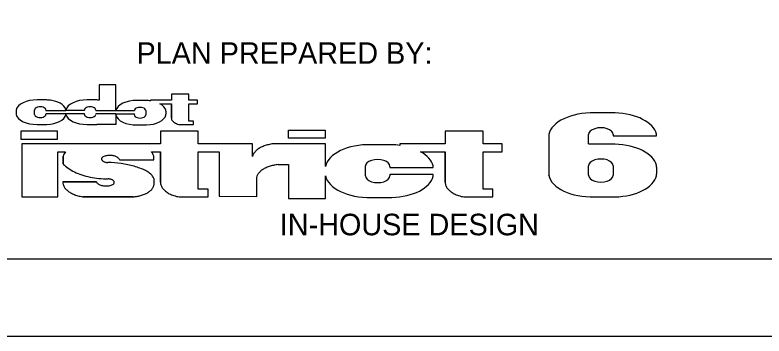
# Model space of a CAD drawing. Extents: x 0 to 34, y 0 to 22.
# Drawn here: x 2.822 to 7.693, y 0 to 2.086 of the extents above; entities that cross this region are included whole.
import ezdxf

# ---------------------------------------------------------------- set-up
doc = ezdxf.new("R2010")
doc.units = 0
for name, color, linetype in [('SC_Scratch9', 7, 'Continuous'), ('SH_Border', 7, 'Continuous'), ('SH_Cut_Line', 7, 'Continuous'), ('SH_Data', 7, 'Continuous')]:
    doc.layers.add(name, color=color, linetype=linetype)

msp = doc.modelspace()

# ---------------------------------------------------------------- linework, layer by layer
at = {"layer": 'SH_Border'}
msp.add_lwpolyline([(0, 0), (34, 0), (34, 22), (0, 22)], close=True, dxfattribs=at)
at = {"layer": 'SH_Cut_Line'}
for p, q in [((3.3699, 1.632), (3.3699, 1.5331)), ((3.4787, 1.632), (3.3699, 1.632)), ((3.4787, 1.4652), (3.4787, 1.632)), ((3.8392, 1.5717), (3.8392, 1.5336)), ((3.9533, 1.5717), (3.8392, 1.5717)), ((3.9533, 1.5336), (3.9533, 1.5717)), ((2.9918, 1.534), (2.9668, 1.534)), ((3.029, 1.534), (2.9918, 1.534)), ((3.3164, 1.534), (3.2914, 1.534)), ((3.3537, 1.534), (3.3164, 1.534)), ((3.6411, 1.5305), (3.616, 1.5305)), ((3.6783, 1.5305), (3.6411, 1.5305)), ((3.8392, 1.5336), (3.703, 1.5336)), ((3.703, 1.5336), (3.703, 1.5286)), ((4.0103, 1.5336), (3.9533, 1.5336)), ((4.0103, 1.5094), (4.0103, 1.5336)), ((2.8294, 1.4686), (2.8294, 1.4407)), ((2.9496, 1.4406), (2.9494, 1.4686)), ((3.0235, 1.4686), (3.0235, 1.4652)), ((3.0235, 1.4652), (3.1541, 1.4652)), ((3.1541, 1.4652), (3.1538, 1.4702)), ((3.1541, 1.4686), (3.1541, 1.4652)), ((3.2741, 1.4652), (3.1541, 1.4652)), ((3.2741, 1.4652), (3.2741, 1.4686)), ((3.3483, 1.4686), (3.3483, 1.4652)), ((3.3483, 1.4652), (3.4787, 1.4652)), ((3.4787, 1.4652), (3.4786, 1.4702)), ((3.4787, 1.4652), (3.4786, 1.4702)), ((3.4787, 1.4652), (3.5987, 1.4652)), ((3.6728, 1.4652), (3.6728, 1.4617)), ((3.6728, 1.4617), (3.6728, 1.4408)), ((3.7648, 1.5094), (3.8392, 1.5094)), ((3.8033, 1.4617), (3.8032, 1.4668)), ((3.8033, 1.4617), (3.8033, 1.4408)), ((3.8392, 1.4174), (3.8392, 1.5094)), ((3.8392, 1.5094), (3.8392, 1.4174)), ((3.9533, 1.397), (3.9533, 1.5094)), ((3.9533, 1.5094), (4.0103, 1.5094)), ((3.0235, 1.4442), (3.0235, 1.4408)), ((3.1541, 1.4442), (3.0235, 1.4442)), ((3.1538, 1.4391), (3.1541, 1.4442)), ((3.2742, 1.4442), (3.1541, 1.4442)), ((3.1541, 1.4442), (3.1541, 1.4407)), ((3.2743, 1.4407), (3.2742, 1.4442)), ((3.3483, 1.4442), (3.3483, 1.4408)), ((3.4787, 1.4442), (3.3483, 1.4442)), ((3.4786, 1.4392), (3.4787, 1.4442)), ((3.4786, 1.4392), (3.4787, 1.4442)), ((3.4787, 1.4442), (3.4957, 1.4442)), ((3.4787, 1.4442), (3.4787, 1.3754)), ((3.4957, 1.4442), (3.5988, 1.4442)), ((3.5988, 1.4372), (3.5988, 1.4442)), ((3.6728, 1.4408), (3.6728, 1.4373)), ((3.8032, 1.4357), (3.8033, 1.4408)), ((6.6439, 1.4497), (6.5898, 1.4497)), ((6.7243, 1.4497), (6.6439, 1.4497)), ((2.9668, 1.3754), (2.9918, 1.3754)), ((2.9918, 1.3754), (3.029, 1.3754)), ((3.2914, 1.3754), (3.3164, 1.3754)), ((3.3164, 1.3754), (3.3537, 1.3754)), ((3.4787, 1.3754), (3.3537, 1.3754)), ((3.4787, 1.3908), (3.4787, 1.3898)), ((3.616, 1.3719), (3.6411, 1.3719)), ((3.6411, 1.3719), (3.6783, 1.3719)), ((3.8951, 1.3736), (3.9828, 1.3736)), ((3.9828, 1.397), (3.9533, 1.397)), ((3.9828, 1.3736), (3.9828, 1.397)), ((2.8606, 1.3321), (2.8606, 1.2797)), ((3.0982, 1.3321), (2.8606, 1.3321)), ((3.0982, 1.2797), (3.0982, 1.3321)), ((3.7683, 1.3321), (3.7683, 1.2499)), ((4.0146, 1.3321), (3.7683, 1.3321)), ((4.0146, 1.2499), (4.0146, 1.3321)), ((4.6014, 1.3371), (4.8386, 1.3371)), ((4.6014, 1.2848), (4.6014, 1.3371)), ((4.8386, 1.3371), (4.8386, 1.2848)), ((5.6201, 1.3321), (5.6201, 1.2499)), ((5.8664, 1.3321), (5.6201, 1.3321)), ((5.8664, 1.2499), (5.8664, 1.3321)), ((2.8606, 1.2797), (3.0982, 1.2797)), ((4.8386, 1.2848), (4.6014, 1.2848)), ((6.2935, 1.3087), (6.2932, 1.0451)), ((6.2935, 1.3087), (6.2935, 1.3103)), ((6.5528, 1.2481), (6.5523, 1.3087)), ((6.7123, 1.3087), (6.7123, 1.3013)), ((6.7123, 1.3013), (6.9943, 1.3013)), ((6.9943, 1.3013), (6.9939, 1.3121)), ((2.866, 1.2499), (2.866, 0.9041)), ((3.5751, 1.2499), (2.866, 1.2499)), ((3.7683, 1.2499), (3.4431, 1.2499)), ((4.3671, 1.2499), (4.0146, 1.2499)), ((4.3671, 1.1659), (4.3671, 1.2499)), ((4.8418, 1.2499), (4.5098, 1.2499)), ((4.8418, 1.1021), (4.8418, 1.2499)), ((5.1923, 1.2431), (5.1382, 1.2431)), ((5.2727, 1.2431), (5.1923, 1.2431)), ((5.6201, 1.2499), (5.3259, 1.2499)), ((5.3259, 1.2499), (5.3259, 1.2389)), ((5.9897, 1.2499), (5.8664, 1.2499)), ((5.9897, 1.1976), (5.9897, 1.2499)), ((6.6439, 1.2465), (6.5898, 1.2465)), ((6.7243, 1.2465), (6.6439, 1.2465)), ((3.101, 0.9041), (3.101, 1.1976)), ((3.101, 1.1976), (3.1514, 1.1973)), ((3.1363, 1.1181), (3.1363, 1.1695)), ((3.1363, 1.1695), (3.1363, 1.1181)), ((3.7091, 1.1976), (3.7683, 1.1976)), ((3.7254, 1.1458), (3.7254, 1.1693)), ((3.7683, 0.9989), (3.7683, 1.1976)), ((3.7683, 1.1976), (3.7683, 0.9989)), ((4.0146, 1.1976), (4.1507, 1.1976)), ((4.0146, 0.9547), (4.0146, 1.1976)), ((4.1507, 1.1976), (4.1507, 0.9091)), ((5.4593, 1.1976), (5.6201, 1.1976)), ((5.6201, 0.9989), (5.6201, 1.1976)), ((5.6201, 1.1976), (5.6201, 0.9989)), ((5.8664, 0.9547), (5.8664, 1.1976)), ((5.8664, 1.1976), (5.9897, 1.1976)), ((3.503, 1.1458), (3.7254, 1.1458)), ((4.5337, 1.1139), (4.6014, 1.1139)), ((4.6014, 1.1139), (4.6014, 0.8939)), ((5.1011, 1.0416), (5.1007, 1.1021)), ((5.2607, 1.1021), (5.2607, 1.0946)), ((5.2607, 1.0946), (5.5427, 1.0946)), ((5.5427, 1.0946), (5.5423, 1.1055)), ((6.5528, 1.0451), (6.5523, 1.1055)), ((6.7123, 1.1055), (6.7123, 1.098)), ((6.7123, 1.098), (6.7123, 1.0527)), ((6.9943, 1.098), (6.9939, 1.1089)), ((6.9943, 1.098), (6.9943, 1.0527)), ((3.7258, 1.0237), (3.7258, 0.9799)), ((4.3942, 0.9074), (4.3942, 1.0299)), ((4.8418, 0.8939), (4.8418, 1.0416)), ((5.2607, 1.0493), (5.2607, 1.0418)), ((5.5427, 1.0493), (5.2607, 1.0493)), ((5.5423, 1.0383), (5.5427, 1.0493)), ((6.2935, 1.0436), (6.2935, 1.0451)), ((6.7123, 1.0527), (6.7123, 1.0452)), ((6.9939, 1.0418), (6.9943, 1.0527)), ((3.1335, 1.0031), (3.3519, 1.0031)), ((3.3519, 1.0031), (3.1335, 1.0031)), ((4.0783, 0.9547), (4.0146, 0.9547)), ((4.0783, 0.9041), (4.0783, 0.9547)), ((5.9301, 0.9547), (5.8664, 0.9547)), ((5.9301, 0.9041), (5.9301, 0.9547)), ((2.866, 0.9041), (3.101, 0.9041)), ((3.5902, 0.9048), (3.2625, 0.9048)), ((3.2625, 0.9048), (3.5902, 0.9048)), ((3.8891, 0.9041), (4.0783, 0.9041)), ((4.1507, 0.9091), (4.3942, 0.9074)), ((4.6014, 0.8939), (4.8418, 0.8939)), ((5.1382, 0.9006), (5.1923, 0.9006)), ((5.1923, 0.9006), (5.2727, 0.9006)), ((5.7409, 0.9041), (5.9301, 0.9041)), ((6.5898, 0.9041), (6.6439, 0.9041)), ((6.6439, 0.9041), (6.7243, 0.9041))]:
    msp.add_line(p, q, dxfattribs=at)
for centre, major_axis, start_param, end_param in [((2.9607, 1.4602), (0.1322, 0), 1.524851, 3.026464), ((3.0229, 1.4602), (0.1321, 0), 1.335517, 1.524729), ((3.0228, 1.4602), (0.1322, 0), 0.793644, 1.335258), ((3.0229, 1.4602), (0.1321, 0), 0.136005, 0.793914), ((3.2854, 1.4602), (0.1322, 0), 1.524851, 3.026464), ((3.3476, 1.4602), (0.1321, 0), 1.401291, 1.524729), ((3.61, 1.4567), (0.1322, 0), 1.524851, 3.026464), ((3.6722, 1.4568), (0.1321, 0), 1.335517, 1.524729), ((2.9864, 1.4687), (0.037, 0), 6.283105, 9.424778), ((3.3111, 1.4687), (0.037, 0), 6.283105, 9.424778), ((3.6357, 1.4652), (0.037, 0), 6.283105, 9.424778), ((3.6722, 1.4568), (0.1321, 0), 0.136005, 0.793914), ((2.9606, 1.4492), (0.1321, 0), 3.256471, 4.758084), ((2.9864, 1.4407), (0.037, 0), 3.141637, 6.283987), ((3.0229, 1.4492), (0.1322, 0), 4.758334, 6.147057), ((3.2853, 1.4492), (0.1321, 0), 3.256471, 4.758084), ((3.3111, 1.4407), (0.037, 0), 3.141637, 6.283987), ((3.6099, 1.4457), (0.1321, 0), 3.256471, 4.758084), ((3.6357, 1.4372), (0.037, 0), 3.141637, 6.283987), ((3.6722, 1.4457), (0.1322, 0), 4.758334, 6.147057), ((3.9234, 1.4174), (0.0842, 0), 3.141424, 3.346546), ((6.5767, 1.2905), (0.2854, 0), 1.524851, 3.026464), ((6.7111, 1.2905), (0.2854, 0), 0.136005, 1.524729), ((3.9226, 1.4173), (0.0834, 0), 3.346554, 3.553012), ((3.922, 1.4172), (0.0827, 0), 3.553048, 3.760669), ((3.9216, 1.417), (0.0822, 0), 3.760726, 3.969135), ((3.9215, 1.417), (0.0821, 0), 3.969205, 4.177885), ((3.9215, 1.417), (0.0822, 0), 4.177955, 4.386342), ((6.6323, 1.3088), (0.08, 0), 6.283105, 9.424778), ((4.5369, 1.1553), (0.171, 0), 2.291032, 2.475806), ((4.5382, 1.1545), (0.1729, 0), 2.107607, 2.291041), ((4.5391, 1.1537), (0.1746, 0), 1.925382, 2.107637), ((4.5395, 1.1531), (0.1758, 0), 1.744044, 1.925429), ((5.125, 1.0838), (0.2854, 0), 1.524851, 3.026464), ((5.2594, 1.0838), (0.2854, 0), 1.335517, 1.524729), ((6.5767, 1.0872), (0.2854, 0), 1.524851, 1.654748), ((6.7111, 1.0872), (0.2854, 0), 0.136005, 1.524729), ((3.2846, 1.1593), (0.1495, 0), 2.843627, 3.018215), ((3.2854, 1.1592), (0.1504, 0), 2.669663, 2.843584), ((3.4381, 1.1371), (0.0656, 0), 1.981803, 2.175423), ((3.4383, 1.1368), (0.0662, 0), 1.789333, 1.981853), ((3.4384, 1.1367), (0.0665, 0), 1.597511, 1.789398), ((3.4384, 1.1366), (0.0665, 0), 1.405775, 1.597582), ((3.4384, 1.1368), (0.0663, 0), 1.213551, 1.405843), ((3.4386, 1.137), (0.0658, 0), 1.020333, 1.213606), ((3.5469, 1.1548), (0.1795, 0), 0.331392, 0.440283), ((3.5408, 1.1536), (0.186, 0), 0.151141, 0.33161), ((4.5332, 1.1565), (0.1666, 0), 2.849219, 3.037192), ((4.5342, 1.1563), (0.1677, 0), 2.66195, 2.849165), ((4.5355, 1.1559), (0.1692, 0), 2.47582, 2.661914), ((5.2594, 1.0838), (0.2854, 0), 0.136005, 0.793914), ((3.4257, 1.151), (0.0404, 0), 3.014859, 3.224424), ((3.4258, 1.151), (0.0405, 0), 3.224512, 3.433796), ((3.4258, 1.151), (0.0405, 0), 2.805634, 3.014772), ((3.426, 1.151), (0.0408, 0), 3.43387, 3.642217), ((3.4261, 1.1509), (0.0409, 0), 2.597484, 2.805565), ((3.4264, 1.1511), (0.0412, 0), 3.642263, 3.849188), ((3.4377, 1.1375), (0.0649, 0), 2.175395, 2.370427), ((3.4268, 1.1513), (0.0417, 0), 3.8492, 4.054466), ((3.4271, 1.1515), (0.0422, 0), 4.054443, 4.258098), ((3.4273, 1.1517), (0.0426, 0), 4.258045, 4.460395), ((3.4273, 1.1519), (0.0429, 0), 4.460322, 4.661876), ((3.4097, 0.8981), (0.4116, 0), 1.316143, 1.533129), ((3.439, 1.1374), (0.0651, 0), 0.82575, 1.020367), ((3.4395, 1.1377), (0.0643, 0), 0.629627, 0.825757), ((3.44, 1.1379), (0.0636, 0), 0.432021, 0.629605), ((3.4406, 1.138), (0.0631, 0), 0.233219, 0.431972), ((3.4104, 0.8995), (0.409, 0), 1.098319, 1.316234), ((5.1806, 1.1021), (0.08, 0), 6.283105, 9.424778), ((6.6323, 1.1055), (0.08, 0), 6.283105, 9.424778), ((3.4214, 1.2035), (0.3237, 0), 3.634473, 3.81594), ((3.424, 1.2047), (0.3271, 0), 3.815952, 3.996157), ((3.4124, 0.9017), (0.4047, 0), 0.878915, 1.098382), ((3.5472, 0.9993), (0.1841, 0), 0.638346, 0.838588), ((4.5617, 1.0202), (0.1691, 0), 2.481267, 2.665571), ((4.5631, 1.0196), (0.1709, 0), 2.298241, 2.481253), ((4.5643, 1.0188), (0.1728, 0), 2.116554, 2.298249), ((4.5652, 1.018), (0.1745, 0), 1.936054, 2.116582), ((4.5657, 1.0173), (0.1757, 0), 1.756445, 1.936099), ((3.4263, 1.2061), (0.3306, 0), 3.996148, 4.175079), ((3.428, 1.2076), (0.3338, 0), 4.175051, 4.352859), ((3.4288, 1.2089), (0.3361, 0), 4.352816, 4.529786), ((3.4291, 1.2096), (0.3374, 0), 4.529734, 4.706252), ((3.5488, 1), (0.182, 0), 0.436558, 0.638324), ((3.5503, 1.0003), (0.1804, 0), 0.233512, 0.436507), ((4.5594, 1.0207), (0.1666, 0), 2.851056, 3.037194), ((4.5604, 1.0206), (0.1676, 0), 2.665607, 2.851004), ((5.125, 1.0599), (0.2853, 0), 3.256471, 4.758084), ((5.1807, 1.0417), (0.0799, 0), 3.141637, 6.283987), ((5.2594, 1.06), (0.2854, 0), 4.758334, 6.147057), ((6.5766, 1.0634), (0.2853, 0), 3.256471, 4.758084), ((6.6323, 1.0451), (0.0799, 0), 3.141637, 6.283987), ((6.7111, 1.0634), (0.2854, 0), 4.758334, 6.147057), ((3.3148, 1.0014), (0.1821, 0), 3.127492, 3.312323), ((3.3132, 1.0012), (0.1805, 0), 3.312325, 3.498251), ((3.4131, 1.0109), (0.0631, 0), 3.367389, 3.566849), ((3.4136, 1.0111), (0.0636, 0), 3.5669, 3.765196), ((3.4142, 1.0113), (0.0643, 0), 3.765219, 3.962057), ((3.4147, 1.0116), (0.0651, 0), 3.96205, 4.157364), ((3.415, 1.0119), (0.0658, 0), 4.15733, 4.351285), ((3.4152, 1.0122), (0.0663, 0), 4.351229, 4.544187), ((3.4153, 1.0123), (0.0665, 0), 4.544118, 4.736579), ((3.4153, 1.0123), (0.0665, 0), 4.736506, 4.92904), ((3.4263, 0.9971), (0.0429, 0), 1.318729, 1.520283), ((3.4153, 1.0121), (0.0662, 0), 4.928973, 5.122138), ((3.4264, 0.9972), (0.0426, 0), 1.116452, 1.318802), ((3.4156, 1.0119), (0.0656, 0), 5.122088, 5.316356), ((3.4266, 0.9974), (0.0422, 0), 0.91285, 1.116505), ((3.4269, 0.9977), (0.0417, 0), 0.707607, 0.912873), ((3.416, 1.0115), (0.0649, 0), 5.316329, 5.512019), ((3.4273, 0.9978), (0.0412, 0), 0.500671, 0.707595), ((3.4275, 0.9981), (0.0409, 0), 5.739076, 5.947158), ((3.4276, 0.998), (0.0408, 0), 0.292277, 0.500624), ((3.4278, 0.998), (0.0405, 0), 5.947227, 6.156365), ((3.4279, 0.998), (0.0405, 0), 0.08292, 0.292204), ((3.428, 0.998), (0.0404, 0), 6.156451, 6.366017), ((3.5773, 0.9895), (0.1496, 0), 5.969049, 6.163238), ((3.9501, 0.9988), (0.1819, 0), 3.141424, 3.346546), ((3.9484, 0.9986), (0.1801, 0), 3.346554, 3.553012), ((5.802, 0.9988), (0.1819, 0), 3.141424, 3.346546), ((5.8002, 0.9986), (0.1801, 0), 3.346554, 3.553012), ((3.3118, 1.0009), (0.179, 0), 3.498271, 3.6852), ((3.3109, 1.0006), (0.1779, 0), 3.685237, 3.872935), ((3.3104, 1.0004), (0.1773, 0), 3.872983, 4.061106), ((3.5738, 0.9907), (0.1537, 0), 5.392868, 5.583529), ((3.5751, 0.9901), (0.152, 0), 5.583539, 5.775628), ((3.5763, 0.9897), (0.1506, 0), 5.775664, 5.968991), ((3.947, 0.9983), (0.1786, 0), 3.553048, 3.760669), ((3.9462, 0.998), (0.1776, 0), 3.760726, 3.969135), ((5.7988, 0.9983), (0.1786, 0), 3.553048, 3.760669), ((5.798, 0.998), (0.1776, 0), 3.760726, 3.969135), ((3.3104, 1.0004), (0.1773, 0), 4.061159, 4.249301), ((3.3107, 1.0007), (0.1778, 0), 4.24935, 4.437102), ((3.5717, 0.9927), (0.158, 0), 4.828409, 5.015661), ((3.572, 0.9922), (0.1569, 0), 5.015606, 5.203669), ((3.5727, 0.9914), (0.1555, 0), 5.203631, 5.392884), ((3.946, 0.9978), (0.1772, 0), 3.969205, 4.177885), ((3.9461, 0.998), (0.1776, 0), 4.177955, 4.386342), ((5.7978, 0.9978), (0.1772, 0), 3.969205, 4.177885), ((5.798, 0.998), (0.1776, 0), 4.177955, 4.386342)]:
    msp.add_ellipse(centre, major_axis=major_axis, ratio=0.558832, start_param=start_param, end_param=end_param, dxfattribs=at)
at = {"layer": 'SH_Data'}
msp.add_lwpolyline([(1.5, 21.5), (33.5, 21.5), (33.5, 0.5), (1.5, 0.5)], close=True, dxfattribs=at)

# ---------------------------------------------------------------- texts
at = {"layer": 'SC_Scratch9'}
for s, p in [('PLAN PREPARED BY:', (3.6125, 1.769)), ('IN-HOUSE DESIGN', (4.5443, 0.6546))]:
    msp.add_text(s, height=0.14, dxfattribs=at).set_placement(p)

doc.saveas('drawing.dxf')
